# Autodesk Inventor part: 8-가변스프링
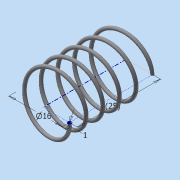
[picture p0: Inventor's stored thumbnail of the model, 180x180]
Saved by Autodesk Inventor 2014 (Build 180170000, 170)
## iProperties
Created: 2015-06
Part Number: 8-가변스프링
Material: 강철, 연강
Document SubType Name: Modeling
Designer: Administrator
Density: 7.86 g/cm^3
Appearance: 강철
Mass: 1.53479 g
Surface Area: 7.89194 cm^2
Volume: 0.195266 cm^3
Author: Administrator
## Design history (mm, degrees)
sketch "스케치1"
  geometry: L1 (0, 0)-(8, 0); L2 (8, 0)-(8, 21.5); L3 (8, 21.5)-(0, 21.5); L4 (0, 21.5)-(0, 0); C1 r 0.5 at (8, 0)
  constraints: 8 end point, 2 parallel, 1 centre point, 1 coincident, 1 horizontal, 1 perpendicular
  dimensions: "d0" = 1 diameter of C1; "d1" = 16 diameter of L2 L4; "d2" = 21.5 distance of L1.end L2.end (derived)
feature "코일1" sketch "스케치1" pitch "d3" = 10; turns "d5" = 5; dims "d4" = 21.5 (= d2), "d6" = 0, angle "d7" = 90 deg, angle "d8" = 90 deg, "d9" = 0, "d10" = 0
sketch "스케치2"
  geometry: L1 (-8.5, 0)-(-7.5, 0) reference; 1 further point
  constraints: 1 horizontal alignment
extrude "돌출1" cut sketch "스케치2" distance "d11" = 10; taper "d12" = 0 deg
node "작업 평면1"
sketch "스케치3"
  geometry: L1 (-7.5, 0)-(-8.5, 0) reference; 1 further point
  constraints: 1 horizontal alignment
extrude "돌출2" cut sketch "스케치3" distance "d14" = 10; taper "d15" = 0 deg
node "솔리드1"
node "절단 모서리 투영1"
node "절단 모서리 투영2"
other parameters: "d13" = 21.5 (= d2)
